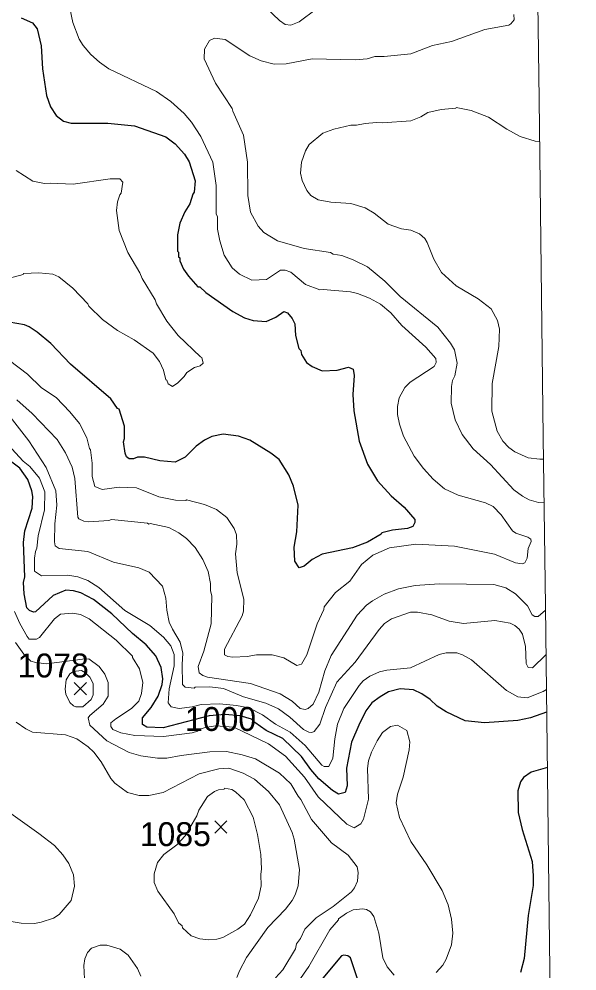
# Model space of a CAD drawing. Extents: x 265.7 to 292.1, y 7676.2 to 7704.2.
# Drawn here: x 290.234 to 292.102, y 7683.775 to 7686.96 of the extents above; entities that cross this region are included whole.
import ezdxf
from ezdxf.enums import TextEntityAlignment as Align

# ---------------------------------------------------------------- set-up
doc = ezdxf.new("R2010")
doc.units = 0
doc.header["$LTSCALE"] = 0.032
for name, color, linetype, lineweight in [('1', 7, 'Continuous', 25), ('2', 7, 'Continuous', 13), ('21', 7, 'Continuous', 25), ('63', 7, 'Continuous', 25)]:
    doc.layers.add(name, color=color, linetype=linetype, lineweight=lineweight)
doc.layers.add('61', color=7, linetype='Continuous')

msp = doc.modelspace()

# ---------------------------------------------------------------- linework, layer by layer
at = {"layer": '1'}
for points in [[(290.241, 7686.9639), (290.2793, 7686.9472), (290.2953, 7686.9272), (290.3088, 7686.8706), (290.3128, 7686.794), (290.3264, 7686.7046), (290.34, 7686.6663), (290.3583, 7686.6376), (290.3831, 7686.6184), (290.4086, 7686.612), (290.5315, 7686.612), (290.6209, 7686.6032), (290.7262, 7686.5657), (290.7565, 7686.5426), (290.7884, 7686.5083), (290.8044, 7686.4828), (290.8235, 7686.4189), (290.8211, 7686.3806), (290.8163, 7686.3742), (290.806, 7686.3423), (290.7892, 7686.3152), (290.7725, 7686.2769), (290.7645, 7686.2386), (290.7645, 7686.1835), (290.7677, 7686.1803), (290.7677, 7686.1644), (290.7725, 7686.1612), (290.7725, 7686.1516), (290.7844, 7686.1237), (290.8012, 7686.0997), (290.8331, 7686.0646), (290.8395, 7686.0638), (290.8602, 7686.0455), (290.9496, 7685.9816), (290.9895, 7685.9601), (291.0182, 7685.9513), (291.0621, 7685.9481), (291.0941, 7685.9633), (291.1212, 7685.9816), (291.1332, 7685.9768), (291.1491, 7685.9585), (291.1571, 7685.9401), (291.1603, 7685.9018), (291.1714, 7685.8579), (291.1778, 7685.8508), (291.1794, 7685.838), (291.197, 7685.8109), (291.2161, 7685.7981), (291.2496, 7685.7829)], [(291.355, 7685.6497), (291.3733, 7685.5475), (291.4013, 7685.4709), (291.434, 7685.4151), (291.4803, 7685.3648), (291.5242, 7685.3273), (291.5593, 7685.2858), (291.5593, 7685.2762), (291.5529, 7685.2627), (291.5353, 7685.2563), (291.4843, 7685.2499), (291.4491, 7685.2411), (291.4468, 7685.2371), (291.4013, 7685.21), (291.3502, 7685.1908), (291.2497, 7685.1701), (291.2161, 7685.1517), (291.189, 7685.1302), (291.1723, 7685.1246), (291.1571, 7685.1462), (291.1555, 7685.1933), (291.1643, 7685.2443), (291.1683, 7685.3337), (291.1531, 7685.3975), (291.1371, 7685.4358), (291.1052, 7685.4861), (291.0773, 7685.5076), (291.0071, 7685.5515), (290.9688, 7685.5643), (290.9177, 7685.5715), (290.8794, 7685.5635), (290.8547, 7685.5515), (290.8275, 7685.5316), (290.7908, 7685.4941), (290.7565, 7685.4773), (290.7054, 7685.4821), (290.6544, 7685.4949), (290.6304, 7685.4941), (290.6177, 7685.4893), (290.6033, 7685.4885), (290.5945, 7685.4957), (290.5897, 7685.5077), (290.5841, 7685.546), (290.5873, 7685.5571), (290.5873, 7685.5986), (290.5698, 7685.6553), (290.5642, 7685.6577), (290.5411, 7685.6896), (290.4062, 7685.8053), (290.3408, 7685.8747), (290.2953, 7685.913), (290.2682, 7685.9306), (290.2522, 7685.9369), (290.2011, 7685.9457)], [(291.2496, 7685.7829), (291.2991, 7685.7853), (291.3374, 7685.7957), (291.3526, 7685.7893), (291.3566, 7685.7678), (291.3518, 7685.7039), (291.355, 7685.6497)], [(292.0007, 7684.6412), (291.9471, 7684.6219), (291.904, 7684.6139), (291.7923, 7684.6059), (291.7284, 7684.6123), (291.6638, 7684.6426), (291.6343, 7684.661), (291.6103, 7684.6833), (291.5824, 7684.7025), (291.5553, 7684.7161), (291.5098, 7684.7192), (291.4715, 7684.7089), (291.4428, 7684.6929), (291.4156, 7684.673), (291.3957, 7684.6458), (291.3717, 7684.598), (291.3478, 7684.5405), (291.3302, 7684.4543), (291.3326, 7684.3953), (291.3263, 7684.3721), (291.3039, 7684.3665), (291.2832, 7684.3793), (291.2385, 7684.4184), (291.2113, 7684.4496), (291.1802, 7684.4926), (291.1172, 7684.5533), (291.0613, 7684.5804), (291.0238, 7684.6067), (291.0125, 7684.618), (290.9748, 7684.6293), (290.9239, 7684.6331), (290.8712, 7684.6293), (290.7166, 7684.5884), (290.6624, 7684.5908), (290.648, 7684.5996), (290.6472, 7684.6219), (290.6767, 7684.657), (290.6998, 7684.6953), (290.7134, 7684.7336), (290.7158, 7684.7528), (290.7102, 7684.7911), (290.6919, 7684.8294), (290.6599, 7684.8661), (290.6137, 7684.9044), (290.5451, 7684.9706), (290.4836, 7685.0177), (290.4413, 7685.0408), (290.4166, 7685.0472), (290.391, 7685.0496), (290.3488, 7685.0321), (290.2889, 7684.977), (290.2825, 7684.9762), (290.2698, 7684.981), (290.2602, 7684.9906), (290.2514, 7685.0369), (290.2498, 7685.0752), (290.2538, 7685.0943), (290.249, 7685.2092), (290.2538, 7685.2475), (290.2785, 7685.3241), (290.2809, 7685.3624), (290.2777, 7685.3816), (290.2642, 7685.4199), (290.237, 7685.4574), (290.2107, 7685.4773)], [(292.003, 7684.4559), (291.9487, 7684.4408), (291.9231, 7684.4224), (291.9136, 7684.4081), (291.904, 7684.3777), (291.9056, 7684.3059), (291.9183, 7684.2485), (291.9519, 7684.1415), (291.9558, 7684.0937), (291.955, 7684.0617), (291.9391, 7683.9612), (291.9255, 7683.8176), (291.9135, 7683.7697)], [(291.3701, 7683.7426), (291.3438, 7683.8192), (291.335, 7683.8263), (291.3215, 7683.8287), (291.3135, 7683.8263), (291.2512, 7683.7513)]]:
    msp.add_lwpolyline(points, dxfattribs=at)
at = {"layer": '2'}
for points in [[(290.4046, 7686.9966), (290.4142, 7686.9488), (290.4357, 7686.8929), (290.4485, 7686.8714), (290.4748, 7686.8418), (290.5036, 7686.8155), (290.5347, 7686.7932), (290.6943, 7686.7174), (290.7422, 7686.6846), (290.7876, 7686.6447), (290.8116, 7686.6152), (290.8427, 7686.5673), (290.8826, 7686.4812), (290.8946, 7686.403), (290.8946, 7686.3072), (290.8985, 7686.2992), (290.8985, 7686.2577), (290.9065, 7686.2178), (290.9209, 7686.17), (290.948, 7686.1277)], [(291.2289, 7686.9934), (291.1723, 7686.9512), (291.1443, 7686.94), (291.1252, 7686.9424), (291.106, 7686.9551), (291.0629, 7686.9966)], [(291.992, 7685.3411), (291.9734, 7685.3426), (291.9423, 7685.352), (291.9199, 7685.364), (291.8912, 7685.3856), (291.8122, 7685.4701), (291.7548, 7685.5228), (291.7173, 7685.5707), (291.6949, 7685.6194), (291.6813, 7685.6752), (291.6821, 7685.7311), (291.6853, 7685.751), (291.6933, 7685.767), (291.7013, 7685.8093), (291.6917, 7685.854), (291.679, 7685.8763), (291.6359, 7685.929), (291.5098, 7686.0319), (291.4587, 7686.083), (291.4013, 7686.1316), (291.3534, 7686.1548), (291.3151, 7686.1692), (291.2864, 7686.1739), (291.2768, 7686.1787), (291.189, 7686.1931), (291.0996, 7686.2186), (291.0534, 7686.2466), (291.035, 7686.2673), (291.0087, 7686.3136), (291.0007, 7686.3694), (290.9991, 7686.4812), (290.9855, 7686.5721), (290.9496, 7686.6519), (290.948, 7686.6615), (290.8922, 7686.7461), (290.8539, 7686.8275), (290.8547, 7686.8594), (290.8714, 7686.8889), (290.8882, 7686.8961), (290.9249, 7686.8921), (291.0071, 7686.837), (291.0454, 7686.8203), (291.0885, 7686.8091), (291.1284, 7686.8107), (291.2161, 7686.8275), (291.3598, 7686.8243), (291.3997, 7686.8267), (291.426, 7686.8355), (291.4571, 7686.8347), (291.5465, 7686.8442), (291.6183, 7686.8722), (291.6822, 7686.8849), (291.7939, 7686.9256), (291.8737, 7686.94), (291.8808, 7686.944), (291.892, 7686.9575), (291.8912, 7686.9759)], [(291.9769, 7686.5491), (291.9623, 7686.5514), (291.912, 7686.5673), (291.8673, 7686.5913), (291.8058, 7686.632), (291.7476, 7686.6543), (291.6981, 7686.6647), (291.6965, 7686.6623), (291.647, 7686.6575), (291.6024, 7686.6479), (291.58, 7686.6336), (291.5465, 7686.6192), (291.4507, 7686.6128), (291.4316, 7686.6144), (291.3933, 7686.6112), (291.3646, 7686.6048), (291.3454, 7686.6048), (291.288, 7686.5913), (291.2512, 7686.5785), (291.2058, 7686.541), (291.193, 7686.5195), (291.1802, 7686.4812), (291.1762, 7686.4445), (291.1818, 7686.4205), (291.1978, 7686.387), (291.2113, 7686.3702), (291.2361, 7686.3559), (291.2784, 7686.3479), (291.3454, 7686.3431), (291.3933, 7686.3287), (291.4236, 7686.3104), (291.4699, 7686.2737), (291.5146, 7686.2585), (291.5465, 7686.2537), (291.5752, 7686.2418), (291.5928, 7686.2258), (291.6008, 7686.213), (291.6231, 7686.1572), (291.6486, 7686.1125), (291.6981, 7686.0678), (291.7715, 7686.0247), (291.8154, 7685.9912), (291.8362, 7685.9513), (291.8425, 7685.9226), (291.8409, 7685.8651), (291.8178, 7685.7407), (291.817, 7685.6481), (291.8354, 7685.5811), (291.8537, 7685.5475), (291.8737, 7685.5268), (291.8944, 7685.5124), (291.9391, 7685.4925), (291.9782, 7685.4877), (291.9902, 7685.4882)], [(290.2251, 7686.454), (290.2809, 7686.4173), (290.3192, 7686.4101), (290.3384, 7686.4117), (290.415, 7686.4077), (290.5395, 7686.4261), (290.5714, 7686.4261), (290.5818, 7686.4149), (290.5762, 7686.3774), (290.5714, 7686.3726), (290.5634, 7686.3487), (290.5602, 7686.32), (290.569, 7686.2529), (290.5985, 7686.1795), (290.6384, 7686.1109)], [(291.1443, 7686.1133), (291.1938, 7686.0726), (291.2417, 7686.0542), (291.252, 7686.0558), (291.3438, 7686.0479), (291.3678, 7686.0423), (291.4077, 7686.0263), (291.4444, 7686.0064), (291.4787, 7685.9776), (291.5154, 7685.9354), (291.596, 7685.8627), (291.6295, 7685.8244), (291.6311, 7685.8109), (291.6239, 7685.7973), (291.5441, 7685.7454), (291.5257, 7685.7271), (291.5066, 7685.6928), (291.5018, 7685.6641), (291.5018, 7685.6369), (291.5082, 7685.605), (291.521, 7685.5651), (291.5577, 7685.4981), (291.588, 7685.4566), (291.6207, 7685.4207), (291.6582, 7685.3888), (291.7045, 7685.3672), (291.7955, 7685.3417), (291.8218, 7685.3297), (291.8481, 7685.3018), (291.8864, 7685.2475), (291.8976, 7685.2403), (291.9375, 7685.2268), (291.9479, 7685.2204), (291.9487, 7685.2124), (291.9391, 7685.1885), (291.9359, 7685.1565), (291.9279, 7685.1414), (291.9183, 7685.1374), (291.896, 7685.1414), (291.8258, 7685.1701), (291.6917, 7685.1972), (291.5625, 7685.2028), (291.4747, 7685.1909), (291.4188, 7685.1661), (291.3805, 7685.135), (291.3422, 7685.0799), (291.2943, 7685.0416), (291.256, 7684.9938), (291.2544, 7684.9842), (291.2321, 7684.9363), (291.1978, 7684.8326), (291.1802, 7684.8015), (291.1643, 7684.7975), (291.1204, 7684.823), (291.0821, 7684.8334), (291.0294, 7684.8334), (290.9975, 7684.827), (290.9496, 7684.8254), (290.9337, 7684.8278), (290.9225, 7684.8334), (290.9225, 7684.8517), (290.9815, 7684.9634), (290.9855, 7684.9794), (290.9871, 7685.0193), (290.9648, 7685.1071), (290.9592, 7685.1709), (290.964, 7685.2028), (290.9624, 7685.2347), (290.9544, 7685.2563), (290.9305, 7685.2922), (290.8954, 7685.3193), (290.8555, 7685.3361), (290.7948, 7685.3512), (290.7924, 7685.3489), (290.7581, 7685.3504), (290.7023, 7685.3616), (290.6272, 7685.3919), (290.5698, 7685.3935), (290.5123, 7685.3864), (290.4876, 7685.3967), (290.4796, 7685.4295), (290.4788, 7685.4749), (290.474, 7685.5188), (290.47, 7685.5236), (290.4613, 7685.5587), (290.4365, 7685.6066), (290.4046, 7685.6465), (290.3583, 7685.6936), (290.3097, 7685.7263), (290.2626, 7685.7726), (290.1684, 7685.842)], [(290.8419, 7685.83), (290.8467, 7685.8284), (290.8507, 7685.8085), (290.8411, 7685.7997), (290.8219, 7685.7949), (290.7956, 7685.7774), (290.7868, 7685.7638), (290.7661, 7685.743), (290.7485, 7685.7311), (290.7334, 7685.7399), (290.7294, 7685.7518), (290.7254, 7685.7534), (290.7182, 7685.7853), (290.7046, 7685.8141), (290.6839, 7685.842), (290.6193, 7685.8875), (290.5634, 7685.9186), (290.5139, 7685.9553), (290.4684, 7685.9992), (290.4645, 7686.0072), (290.4142, 7686.0598), (290.3671, 7686.0981), (290.348, 7686.1069), (290.3001, 7686.1109), (290.249, 7686.1093), (290.2482, 7686.1061), (290.1852, 7686.0894)], [(290.6384, 7686.1109), (290.6464, 7686.0918), (290.6895, 7686.0207), (290.6943, 7686.0072), (290.7294, 7685.9497), (290.7669, 7685.9018), (290.8419, 7685.83)], [(290.948, 7686.1277), (290.972, 7686.1069), (291.0135, 7686.0862), (291.0629, 7686.0894), (291.1092, 7686.1197), (291.1252, 7686.1205), (291.1443, 7686.1133)], [(291.9965, 7684.9823), (291.9718, 7684.9618), (291.9614, 7684.9618), (291.9527, 7684.9666), (291.9367, 7684.997), (291.896, 7685.0368), (291.8641, 7685.0568), (291.8242, 7685.068), (291.6407, 7685.0704), (291.5609, 7685.0648), (291.505, 7685.0536), (291.4571, 7685.036), (291.4172, 7685.0137), (291.3981, 7684.9993), (291.3662, 7684.9658), (291.2792, 7684.831), (291.2576, 7684.7799), (291.2385, 7684.7081), (291.2185, 7684.6682), (291.2018, 7684.6538), (291.1922, 7684.6506), (291.1754, 7684.6538), (291.1483, 7684.6786), (291.1084, 7684.7025), (291.0087, 7684.7376), (290.865, 7684.7584), (290.8491, 7684.7639), (290.8371, 7684.7727), (290.8339, 7684.7943), (290.8531, 7684.8453), (290.8778, 7684.9363), (290.8794, 7685.0297), (290.8754, 7685.048), (290.8754, 7685.072), (290.8674, 7685.1119), (290.8491, 7685.1518), (290.8235, 7685.1917), (290.7948, 7685.222), (290.7693, 7685.2411), (290.7358, 7685.2587), (290.6735, 7685.2722), (290.6687, 7685.2706), (290.664, 7685.2738), (290.5443, 7685.2858), (290.5347, 7685.2826), (290.4677, 7685.2778), (290.4509, 7685.2802), (290.4349, 7685.2882), (290.4309, 7685.2938), (290.4206, 7685.4231), (290.4118, 7685.4614), (290.3894, 7685.5092), (290.3615, 7685.5539), (290.2785, 7685.6401), (290.2267, 7685.6864)], [(290.1971, 7685.6393), (290.2674, 7685.5491), (290.3248, 7685.4598), (290.3575, 7685.3816), (290.3607, 7685.3337), (290.3543, 7685.2715), (290.3527, 7685.2108), (290.3551, 7685.198), (290.3687, 7685.1885), (290.4645, 7685.1789), (290.5506, 7685.143), (290.6352, 7685.1238), (290.6703, 7685.1095), (290.715, 7685.0624), (290.7262, 7685.0225), (290.7294, 7684.9826), (290.7374, 7684.9427), (290.7477, 7684.9188), (290.7733, 7684.8749), (290.7828, 7684.839), (290.7804, 7684.8007), (290.782, 7684.7336), (290.7908, 7684.7248), (290.8204, 7684.7217), (290.8235, 7684.7248), (290.873, 7684.7256), (290.9193, 7684.7201), (290.9863, 7684.6921), (291.0605, 7684.6714), (291.1028, 7684.6522), (291.1411, 7684.6243), (291.1866, 7684.5836), (291.205, 7684.574), (291.2145, 7684.5732), (291.2225, 7684.5764), (291.2417, 7684.6012), (291.26, 7684.657), (291.2983, 7684.7416), (291.3598, 7684.8086), (291.4396, 7684.918), (291.4579, 7684.9379), (291.4811, 7684.9531), (291.5449, 7684.9754), (291.5688, 7684.9754), (291.6167, 7684.9674), (291.6742, 7684.9459), (291.722, 7684.9379), (291.8274, 7684.9483), (291.8785, 7684.9387), (291.8944, 7684.9307), (291.9088, 7684.9187), (291.9199, 7684.902), (291.9295, 7684.8613), (291.9319, 7684.8038), (291.9383, 7684.7903), (291.9535, 7684.7895), (291.9983, 7684.8334)], [(291.9998, 7684.7175), (291.9887, 7684.7106), (291.9351, 7684.6889), (291.904, 7684.6929), (291.8665, 7684.7137), (291.7492, 7684.8158), (291.7189, 7684.8334), (291.6997, 7684.8398), (291.6646, 7684.8398), (291.6407, 7684.8342), (291.5449, 7684.7895), (291.4651, 7684.7823), (291.4412, 7684.7767), (291.4092, 7684.7616), (291.3869, 7684.7456), (291.3733, 7684.7304), (291.3215, 7684.653), (291.3007, 7684.6012), (291.2911, 7684.5517), (291.2848, 7684.4879), (291.272, 7684.4599), (291.256, 7684.4591), (291.2481, 7684.4639), (291.1922, 7684.5301), (291.1419, 7684.574), (291.0933, 7684.6012), (291.0494, 7684.6323), (291.004, 7684.6554), (290.9618, 7684.6634), (290.9056, 7684.669), (290.8438, 7684.6671), (290.8139, 7684.6596), (290.7708, 7684.654), (290.7437, 7684.6594), (290.7334, 7684.673), (290.7374, 7684.7193), (290.7541, 7684.7959), (290.7533, 7684.8342), (290.7421, 7684.8629), (290.7174, 7684.8924), (290.6719, 7684.9307), (290.5881, 7684.981), (290.5012, 7685.0584), (290.4645, 7685.0823), (290.4309, 7685.0935), (290.3974, 7685.0999), (290.3097, 7685.0975), (290.2857, 7685.1135), (290.2857, 7685.1565), (290.2889, 7685.1789), (290.2937, 7685.1901), (290.2985, 7685.2316), (290.3192, 7685.3177), (290.3208, 7685.3784), (290.3025, 7685.4247), (290.2705, 7685.463), (290.2482, 7685.4813), (290.2107, 7685.5228)], [(290.2195, 7684.9778), (290.237, 7684.9379), (290.261, 7684.894), (290.2682, 7684.886), (290.2929, 7684.8852), (290.3033, 7684.8916), (290.3527, 7684.9531), (290.3735, 7684.969), (290.4134, 7684.973), (290.4405, 7684.9682), (290.4693, 7684.9539), (290.5594, 7684.882), (290.6145, 7684.8286), (290.6145, 7684.8238), (290.6376, 7684.7863), (290.6488, 7684.74), (290.6448, 7684.7033), (290.6352, 7684.6786), (290.6105, 7684.6538), (290.5586, 7684.6195), (290.5419, 7684.6052), (290.5411, 7684.5932), (290.5482, 7684.5828), (290.5746, 7684.5716), (290.6225, 7684.5637), (290.7182, 7684.5597), (290.814, 7684.5724), (290.8315, 7684.5772), (290.8371, 7684.5828), (290.8577, 7684.5898), (290.8915, 7684.5954), (290.9533, 7684.5916), (291.0693, 7684.5357), (291.126, 7684.4942), (291.1898, 7684.424), (291.2353, 7684.3578), (291.3318, 7684.2668), (291.3566, 7684.2548), (291.3781, 7684.2676), (291.3877, 7684.2836), (291.4045, 7684.3506), (291.4013, 7684.4527), (291.4045, 7684.4783), (291.414, 7684.507), (291.4332, 7684.5453), (291.4515, 7684.5732), (291.4779, 7684.5932), (291.5018, 7684.5972), (291.5321, 7684.5796), (291.5425, 7684.5421), (291.5401, 7684.515), (291.5202, 7684.424), (291.501, 7684.3666), (291.497, 7684.3378), (291.5082, 7684.2884), (291.5465, 7684.2086), (291.6, 7684.1304), (291.651, 7684.0442), (291.671, 7683.9963), (291.6821, 7683.9484), (291.6861, 7683.9022), (291.6821, 7683.8623), (291.6646, 7683.8144), (291.6534, 7683.7952), (291.6311, 7683.7705)], [(291.3478, 7684.0402), (291.3574, 7684.053), (291.367, 7684.0761), (291.3701, 7684.1048), (291.3662, 7684.124), (291.3358, 7684.1623), (291.28, 7684.2046), (291.2129, 7684.282), (291.1778, 7684.349), (291.1683, 7684.3602), (291.1443, 7684.4017), (291.106, 7684.4368), (291.0262, 7684.4855), (290.9815, 7684.499), (290.9289, 7684.5094), (290.873, 7684.5086), (290.7773, 7684.4966), (290.7294, 7684.4871), (290.6975, 7684.4871), (290.6416, 7684.495), (290.6033, 7684.5062), (290.5283, 7684.5453), (290.4716, 7684.598), (290.4661, 7684.6219), (290.4708, 7684.6299), (290.5155, 7684.6682), (290.5331, 7684.6945), (290.5331, 7684.74), (290.5219, 7684.7687), (290.5028, 7684.7943), (290.468, 7684.8192), (290.4463, 7684.8191), (290.3263, 7684.8034), (290.2905, 7684.8071), (290.2733, 7684.8123), (290.2505, 7684.8353), (290.2227, 7684.8741)], [(290.2251, 7684.6083), (290.257, 7684.5852), (290.2793, 7684.574), (290.3895, 7684.5653), (290.4278, 7684.5517)], [(290.4278, 7684.5517), (290.4661, 7684.5253), (290.4844, 7684.5078), (290.5091, 7684.4751), (290.5411, 7684.4192), (290.5546, 7684.4033), (290.5969, 7684.3729)], [(290.5969, 7684.3729), (290.6368, 7684.3626), (290.6687, 7684.3626), (290.7166, 7684.3721), (290.8379, 7684.4344), (290.9033, 7684.4519), (290.9369, 7684.4535), (290.9847, 7684.4376), (291.023, 7684.4168), (291.0693, 7684.3761), (291.106, 7684.3307), (291.1491, 7684.2389), (291.1555, 7684.2165), (291.173, 7684.1152), (291.1683, 7684.0601), (291.1587, 7684.0298), (291.1491, 7684.0107), (291.1268, 7683.9819), (291.0677, 7683.9205), (290.9959, 7683.8208), (290.972, 7683.7761), (290.964, 7683.7537)], [(290.0735, 7683.9636), (290.241, 7683.9349), (290.2857, 7683.9341), (290.3081, 7683.9381), (290.3496, 7683.9524), (290.3687, 7683.9644), (290.4086, 7684.0115), (290.4198, 7684.0586), (290.4166, 7684.0969), (290.4014, 7684.1352), (290.3807, 7684.1639), (290.3527, 7684.195), (290.3009, 7684.2357), (290.2067, 7684.3027)], [(291.1595, 7683.8495), (291.1635, 7683.8662), (291.1762, 7683.8838), (291.1906, 7683.9157), (291.2289, 7683.9532), (291.2864, 7683.9907), (291.3478, 7684.0402)], [(291.4906, 7683.7609), (291.4667, 7683.7888), (291.4523, 7683.8192), (291.4388, 7683.9022), (291.422, 7683.958), (291.4108, 7683.9732), (291.3973, 7683.9811), (291.3837, 7683.9827), (291.3534, 7683.9795), (291.3302, 7683.9692), (291.3039, 7683.95), (291.3039, 7683.946), (291.2752, 7683.9133), (291.2042, 7683.7904), (291.1587, 7683.725)], [(290.6416, 7683.7577), (290.6312, 7683.7841), (290.6001, 7683.8287), (290.573, 7683.8487), (290.5283, 7683.8614), (290.506, 7683.8614), (290.4772, 7683.8519), (290.4637, 7683.8375), (290.4549, 7683.816), (290.4517, 7683.7936), (290.4549, 7683.7266)], [(291.0933, 7683.7521), (291.118, 7683.7793), (291.1595, 7683.8495)]]:
    msp.add_lwpolyline(points, dxfattribs=at)
for points in [[(290.3926, 7684.7493), (290.404, 7684.7696), (290.417, 7684.7774), (290.443, 7684.7804), (290.4565, 7684.7731), (290.4708, 7684.7584), (290.482, 7684.7368), (290.482, 7684.6993), (290.4756, 7684.6834), (290.4477, 7684.6594), (290.4246, 7684.6594), (290.4166, 7684.6626), (290.4046, 7684.6738), (290.391, 7684.7017), (290.3886, 7684.7177)], [(290.7904, 7684.2273), (290.7623, 7684.1971), (290.719, 7684.1655), (290.6975, 7684.1383), (290.6863, 7684.1), (290.6871, 7684.0713), (290.6991, 7684.0426), (290.7533, 7683.966), (290.7685, 7683.9365), (290.7804, 7683.9269), (290.7812, 7683.9197), (290.8108, 7683.8926), (290.8395, 7683.883), (290.8682, 7683.8798), (290.897, 7683.8814), (290.9161, 7683.8878), (290.9672, 7683.9149), (290.9895, 7683.9325), (291.0095, 7683.9628), (291.0358, 7684.0187), (291.0454, 7684.0601), (291.0438, 7684.0985), (291.0462, 7684.1176), (291.0438, 7684.1655), (291.0326, 7684.2325), (291.0182, 7684.29), (290.9879, 7684.3474), (290.9592, 7684.3745), (290.9464, 7684.3825), (290.9225, 7684.3873), (290.9209, 7684.3833), (290.9025, 7684.3817), (290.889, 7684.3761), (290.865, 7684.3594), (290.8363, 7684.3139), (290.8299, 7684.2947)]]:
    msp.add_lwpolyline(points, close=True, dxfattribs=at)
at = {"layer": '21'}
for p, q in [((290.4186, 7684.7405), (290.4598, 7684.6993)), ((290.4598, 7684.7405), (290.4186, 7684.6993)), ((290.8893, 7684.2779), (290.9305, 7684.2367)), ((290.9305, 7684.2779), (290.8893, 7684.2367))]:
    msp.add_line(p, q, dxfattribs=at)
at = {"layer": '63', "lineweight": 13}
msp.add_lwpolyline([(291.9681, 7687.2556), (291.9752, 7686.6906), (291.9822, 7686.1257), (291.9893, 7685.5608), (291.9963, 7684.9959), (292.0034, 7684.431), (292.0104, 7683.866), (292.0175, 7683.3011), (292.0245, 7682.7362), (292.0316, 7682.1713), (292.0386, 7681.6064), (292.0457, 7681.0414), (292.0527, 7680.4765), (292.0598, 7679.9116), (292.0668, 7679.3467), (292.0739, 7678.7818), (292.081, 7678.2168), (292.088, 7677.6519), (292.0951, 7677.087), (292.1022, 7676.5221)], dxfattribs=at)

# ---------------------------------------------------------------- texts
at = {"layer": '61'}
for s, p in [('1078', (290.3487, 7684.7574)), ('1000', (290.9089, 7684.5784)), ('1085', (290.7575, 7684.1931))]:
    msp.add_text(s, height=0.08, dxfattribs=at).set_placement(p, align=Align.CENTER)

doc.saveas('drawing.dxf')
